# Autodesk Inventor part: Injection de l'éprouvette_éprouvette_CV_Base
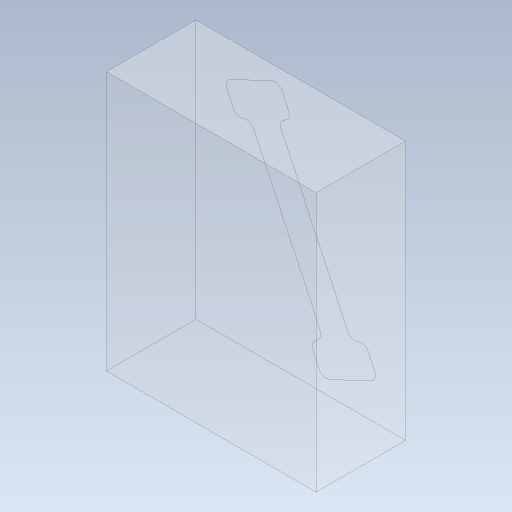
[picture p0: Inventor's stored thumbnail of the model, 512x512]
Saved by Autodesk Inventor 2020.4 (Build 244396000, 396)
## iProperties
Created: 2021-10
Part Number: Injection de l'éprouvette_éprouvette_CV_Base
Material: Générique
Document SubType Name: Modeling
Designer: mel
Density: 1 g/cm^3
Appearance: Par défaut
Author: mel
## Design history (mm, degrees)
node "Injection de l'éprouvette_éprouvette_MP"
feature "Solide7::Injection de l'éprouvette_éprouvette_MP"
tag "FonctionRepérage2"
node "Solide2"
feature "Injection de l'éprouvette_éprouvette_MP_Corps"
